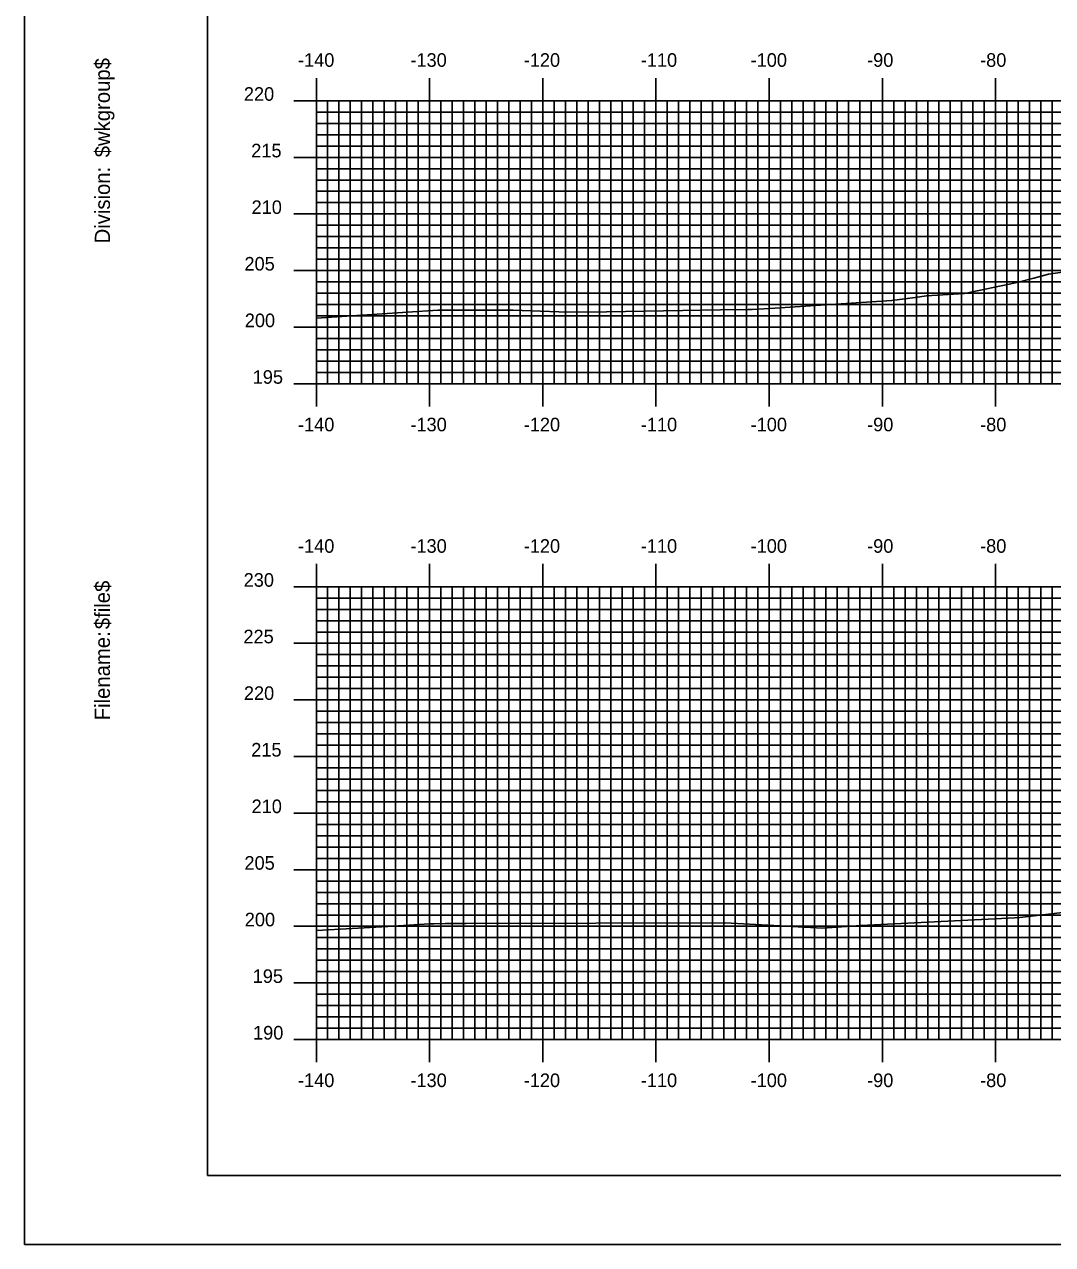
# Model space of a CAD drawing. Extents: x 852529 to 852872, y 364785 to 365005.
# Drawn here: x 852528.9 to 852619.8, y 364785.1 to 364892.9 of the extents above; entities that cross this region are included whole.
import ezdxf

# ---------------------------------------------------------------- set-up
doc = ezdxf.new("R2010")
doc.units = 0
for name, color, linetype in [('BORDER', 7, 'Continuous'), ('H_V ANNOTATION', 7, 'Continuous'), ('MAJOR', 7, 'Continuous'), ('MINOR', 7, 'Continuous'), ('PLOT BOUNDARY', 7, 'Continuous'), ('S_Roadway_Centerline', 7, 'Continuous')]:
    doc.layers.add(name, color=color, linetype=linetype)

msp = doc.modelspace()

# ---------------------------------------------------------------- linework, layer by layer
at = {"layer": 'BORDER'}
msp.add_lwpolyline([(852545.13, 364791.23), (852865.13, 364791.23), (852865.13, 365001.23), (852545.13, 365001.23)], close=True, dxfattribs=at)
at = {"layer": 'MAJOR'}
for p, q in [((852554.73, 364888.17), (852554.73, 364886.16)), ((852564.73, 364888.17), (852564.73, 364886.16)), ((852574.73, 364888.17), (852574.73, 364886.16)), ((852584.73, 364888.17), (852584.73, 364886.16)), ((852594.73, 364888.17), (852594.73, 364886.16)), ((852604.73, 364888.17), (852604.73, 364886.16)), ((852614.73, 364888.17), (852614.73, 364886.16)), ((852552.73, 364886.16), (852554.73, 364886.16)), ((852554.73, 364886.16), (852694.73, 364886.16)), ((852554.73, 364861.16), (852554.73, 364886.16)), ((852554.73, 364861.16), (852554.73, 364886.16)), ((852554.73, 364886.16), (852694.73, 364886.16)), ((852564.73, 364861.16), (852564.73, 364886.16)), ((852574.73, 364861.16), (852574.73, 364886.16)), ((852584.73, 364861.16), (852584.73, 364886.16)), ((852594.73, 364861.16), (852594.73, 364886.16)), ((852604.73, 364861.16), (852604.73, 364886.16)), ((852614.73, 364861.16), (852614.73, 364886.16)), ((852552.73, 364881.16), (852554.73, 364881.16)), ((852554.73, 364881.16), (852694.73, 364881.16)), ((852552.73, 364876.16), (852554.73, 364876.16)), ((852554.73, 364876.16), (852694.73, 364876.16)), ((852552.73, 364871.16), (852554.73, 364871.16)), ((852554.73, 364871.16), (852694.73, 364871.16)), ((852552.73, 364866.16), (852554.73, 364866.16)), ((852554.73, 364866.16), (852694.73, 364866.16)), ((852552.73, 364861.16), (852554.73, 364861.16)), ((852554.73, 364861.16), (852694.73, 364861.16)), ((852554.73, 364861.16), (852694.73, 364861.16)), ((852554.73, 364859.16), (852554.73, 364861.16)), ((852564.73, 364859.16), (852564.73, 364861.16)), ((852574.73, 364859.16), (852574.73, 364861.16)), ((852584.73, 364859.16), (852584.73, 364861.16)), ((852594.73, 364859.16), (852594.73, 364861.16)), ((852604.73, 364859.16), (852604.73, 364861.16)), ((852614.73, 364859.16), (852614.73, 364861.16)), ((852554.73, 364845.24), (852554.73, 364843.23)), ((852564.73, 364845.24), (852564.73, 364843.23)), ((852574.73, 364845.24), (852574.73, 364843.23)), ((852584.73, 364845.24), (852584.73, 364843.23)), ((852594.73, 364845.24), (852594.73, 364843.23)), ((852604.73, 364845.24), (852604.73, 364843.23)), ((852614.73, 364845.24), (852614.73, 364843.23)), ((852552.73, 364843.23), (852554.73, 364843.23)), ((852554.73, 364843.23), (852834.73, 364843.23)), ((852554.73, 364803.23), (852554.73, 364843.23)), ((852554.73, 364803.23), (852554.73, 364843.23)), ((852554.73, 364843.23), (852834.73, 364843.23)), ((852564.73, 364803.23), (852564.73, 364843.23)), ((852574.73, 364803.23), (852574.73, 364843.23)), ((852584.73, 364803.23), (852584.73, 364843.23)), ((852594.73, 364803.23), (852594.73, 364843.23)), ((852604.73, 364803.23), (852604.73, 364843.23)), ((852614.73, 364803.23), (852614.73, 364843.23)), ((852552.73, 364838.23), (852554.73, 364838.23)), ((852554.73, 364838.23), (852834.73, 364838.23)), ((852552.73, 364833.23), (852554.73, 364833.23)), ((852554.73, 364833.23), (852834.73, 364833.23)), ((852552.73, 364828.23), (852554.73, 364828.23)), ((852554.73, 364828.23), (852834.73, 364828.23)), ((852552.73, 364823.23), (852554.73, 364823.23)), ((852554.73, 364823.23), (852834.73, 364823.23)), ((852552.73, 364818.23), (852554.73, 364818.23)), ((852554.73, 364818.23), (852834.73, 364818.23)), ((852552.73, 364813.23), (852554.73, 364813.23)), ((852554.73, 364813.23), (852834.73, 364813.23)), ((852552.73, 364808.23), (852554.73, 364808.23)), ((852554.73, 364808.23), (852834.73, 364808.23)), ((852552.73, 364803.23), (852554.73, 364803.23)), ((852554.73, 364803.23), (852834.73, 364803.23)), ((852554.73, 364803.23), (852834.73, 364803.23)), ((852554.73, 364801.23), (852554.73, 364803.23)), ((852564.73, 364801.23), (852564.73, 364803.23)), ((852574.73, 364801.23), (852574.73, 364803.23)), ((852584.73, 364801.23), (852584.73, 364803.23)), ((852594.73, 364801.23), (852594.73, 364803.23)), ((852604.73, 364801.23), (852604.73, 364803.23)), ((852614.73, 364801.23), (852614.73, 364803.23))]:
    msp.add_line(p, q, dxfattribs=at)
at = {"layer": 'MINOR'}
for p, q in [((852555.73, 364861.16), (852555.73, 364886.16)), ((852556.73, 364861.16), (852556.73, 364886.16)), ((852557.73, 364861.16), (852557.73, 364886.16)), ((852558.73, 364861.16), (852558.73, 364886.16)), ((852559.73, 364861.16), (852559.73, 364886.16)), ((852560.73, 364861.16), (852560.73, 364886.16)), ((852561.73, 364861.16), (852561.73, 364886.16)), ((852562.73, 364861.16), (852562.73, 364886.16)), ((852563.73, 364861.16), (852563.73, 364886.16)), ((852565.73, 364861.16), (852565.73, 364886.16)), ((852566.73, 364861.16), (852566.73, 364886.16)), ((852567.73, 364861.16), (852567.73, 364886.16)), ((852568.73, 364861.16), (852568.73, 364886.16)), ((852569.73, 364861.16), (852569.73, 364886.16)), ((852570.73, 364861.16), (852570.73, 364886.16)), ((852571.73, 364861.16), (852571.73, 364886.16)), ((852572.73, 364861.16), (852572.73, 364886.16)), ((852573.73, 364861.16), (852573.73, 364886.16)), ((852575.73, 364861.16), (852575.73, 364886.16)), ((852576.73, 364861.16), (852576.73, 364886.16)), ((852577.73, 364861.16), (852577.73, 364886.16)), ((852578.73, 364861.16), (852578.73, 364886.16)), ((852579.73, 364861.16), (852579.73, 364886.16)), ((852580.73, 364861.16), (852580.73, 364886.16)), ((852581.73, 364861.16), (852581.73, 364886.16)), ((852582.73, 364861.16), (852582.73, 364886.16)), ((852583.73, 364861.16), (852583.73, 364886.16)), ((852585.73, 364861.16), (852585.73, 364886.16)), ((852586.73, 364861.16), (852586.73, 364886.16)), ((852587.73, 364861.16), (852587.73, 364886.16)), ((852588.73, 364861.16), (852588.73, 364886.16)), ((852589.73, 364861.16), (852589.73, 364886.16)), ((852590.73, 364861.16), (852590.73, 364886.16)), ((852591.73, 364861.16), (852591.73, 364886.16)), ((852592.73, 364861.16), (852592.73, 364886.16)), ((852593.73, 364861.16), (852593.73, 364886.16)), ((852595.73, 364861.16), (852595.73, 364886.16)), ((852596.73, 364861.16), (852596.73, 364886.16)), ((852597.73, 364861.16), (852597.73, 364886.16)), ((852598.73, 364861.16), (852598.73, 364886.16)), ((852599.73, 364861.16), (852599.73, 364886.16)), ((852600.73, 364861.16), (852600.73, 364886.16)), ((852601.73, 364861.16), (852601.73, 364886.16)), ((852602.73, 364861.16), (852602.73, 364886.16)), ((852603.73, 364861.16), (852603.73, 364886.16)), ((852605.73, 364861.16), (852605.73, 364886.16)), ((852606.73, 364861.16), (852606.73, 364886.16)), ((852607.73, 364861.16), (852607.73, 364886.16)), ((852608.73, 364861.16), (852608.73, 364886.16)), ((852609.73, 364861.16), (852609.73, 364886.16)), ((852610.73, 364861.16), (852610.73, 364886.16)), ((852611.73, 364861.16), (852611.73, 364886.16)), ((852612.73, 364861.16), (852612.73, 364886.16)), ((852613.73, 364861.16), (852613.73, 364886.16)), ((852615.73, 364861.16), (852615.73, 364886.16)), ((852616.73, 364861.16), (852616.73, 364886.16)), ((852617.73, 364861.16), (852617.73, 364886.16)), ((852618.73, 364861.16), (852618.73, 364886.16)), ((852619.73, 364861.16), (852619.73, 364886.16)), ((852554.73, 364885.16), (852694.73, 364885.16)), ((852554.73, 364885.16), (852556.73, 364885.16)), ((852554.73, 364884.16), (852694.73, 364884.16)), ((852554.73, 364884.16), (852556.73, 364884.16)), ((852554.73, 364883.16), (852694.73, 364883.16)), ((852554.73, 364883.16), (852556.73, 364883.16)), ((852554.73, 364882.16), (852694.73, 364882.16)), ((852554.73, 364882.16), (852556.73, 364882.16)), ((852554.73, 364880.16), (852694.73, 364880.16)), ((852554.73, 364880.16), (852556.73, 364880.16)), ((852554.73, 364879.16), (852694.73, 364879.16)), ((852554.73, 364879.16), (852556.73, 364879.16)), ((852554.73, 364878.16), (852694.73, 364878.16)), ((852554.73, 364878.16), (852556.73, 364878.16)), ((852554.73, 364877.16), (852694.73, 364877.16)), ((852554.73, 364877.16), (852556.73, 364877.16)), ((852554.73, 364875.16), (852694.73, 364875.16)), ((852554.73, 364875.16), (852556.73, 364875.16)), ((852554.73, 364874.16), (852694.73, 364874.16)), ((852554.73, 364874.16), (852556.73, 364874.16)), ((852554.73, 364873.16), (852694.73, 364873.16)), ((852554.73, 364873.16), (852556.73, 364873.16)), ((852554.73, 364872.16), (852694.73, 364872.16)), ((852554.73, 364872.16), (852556.73, 364872.16)), ((852554.73, 364870.16), (852694.73, 364870.16)), ((852554.73, 364870.16), (852556.73, 364870.16)), ((852554.73, 364869.16), (852694.73, 364869.16)), ((852554.73, 364869.16), (852556.73, 364869.16)), ((852554.73, 364868.16), (852694.73, 364868.16)), ((852554.73, 364868.16), (852556.73, 364868.16)), ((852554.73, 364867.16), (852694.73, 364867.16)), ((852554.73, 364867.16), (852556.73, 364867.16)), ((852554.73, 364865.16), (852694.73, 364865.16)), ((852554.73, 364865.16), (852556.73, 364865.16)), ((852554.73, 364864.16), (852694.73, 364864.16)), ((852554.73, 364864.16), (852556.73, 364864.16)), ((852554.73, 364863.16), (852694.73, 364863.16)), ((852554.73, 364863.16), (852556.73, 364863.16)), ((852554.73, 364862.16), (852694.73, 364862.16)), ((852554.73, 364862.16), (852556.73, 364862.16)), ((852555.73, 364803.23), (852555.73, 364843.23)), ((852556.73, 364803.23), (852556.73, 364843.23)), ((852557.73, 364803.23), (852557.73, 364843.23)), ((852558.73, 364803.23), (852558.73, 364843.23)), ((852559.73, 364803.23), (852559.73, 364843.23)), ((852560.73, 364803.23), (852560.73, 364843.23)), ((852561.73, 364803.23), (852561.73, 364843.23)), ((852562.73, 364803.23), (852562.73, 364843.23)), ((852563.73, 364803.23), (852563.73, 364843.23)), ((852565.73, 364803.23), (852565.73, 364843.23)), ((852566.73, 364803.23), (852566.73, 364843.23)), ((852567.73, 364803.23), (852567.73, 364843.23)), ((852568.73, 364803.23), (852568.73, 364843.23)), ((852569.73, 364803.23), (852569.73, 364843.23)), ((852570.73, 364803.23), (852570.73, 364843.23)), ((852571.73, 364803.23), (852571.73, 364843.23)), ((852572.73, 364803.23), (852572.73, 364843.23)), ((852573.73, 364803.23), (852573.73, 364843.23)), ((852575.73, 364803.23), (852575.73, 364843.23)), ((852576.73, 364803.23), (852576.73, 364843.23)), ((852577.73, 364803.23), (852577.73, 364843.23)), ((852578.73, 364803.23), (852578.73, 364843.23)), ((852579.73, 364803.23), (852579.73, 364843.23)), ((852580.73, 364803.23), (852580.73, 364843.23)), ((852581.73, 364803.23), (852581.73, 364843.23)), ((852582.73, 364803.23), (852582.73, 364843.23)), ((852583.73, 364803.23), (852583.73, 364843.23)), ((852585.73, 364803.23), (852585.73, 364843.23)), ((852586.73, 364803.23), (852586.73, 364843.23)), ((852587.73, 364803.23), (852587.73, 364843.23)), ((852588.73, 364803.23), (852588.73, 364843.23)), ((852589.73, 364803.23), (852589.73, 364843.23)), ((852590.73, 364803.23), (852590.73, 364843.23)), ((852591.73, 364803.23), (852591.73, 364843.23)), ((852592.73, 364803.23), (852592.73, 364843.23)), ((852593.73, 364803.23), (852593.73, 364843.23)), ((852595.73, 364803.23), (852595.73, 364843.23)), ((852596.73, 364803.23), (852596.73, 364843.23)), ((852597.73, 364803.23), (852597.73, 364843.23)), ((852598.73, 364803.23), (852598.73, 364843.23)), ((852599.73, 364803.23), (852599.73, 364843.23)), ((852600.73, 364803.23), (852600.73, 364843.23)), ((852601.73, 364803.23), (852601.73, 364843.23)), ((852602.73, 364803.23), (852602.73, 364843.23)), ((852603.73, 364803.23), (852603.73, 364843.23)), ((852605.73, 364803.23), (852605.73, 364843.23)), ((852606.73, 364803.23), (852606.73, 364843.23)), ((852607.73, 364803.23), (852607.73, 364843.23)), ((852608.73, 364803.23), (852608.73, 364843.23)), ((852609.73, 364803.23), (852609.73, 364843.23)), ((852610.73, 364803.23), (852610.73, 364843.23)), ((852611.73, 364803.23), (852611.73, 364843.23)), ((852612.73, 364803.23), (852612.73, 364843.23)), ((852613.73, 364803.23), (852613.73, 364843.23)), ((852615.73, 364803.23), (852615.73, 364843.23)), ((852616.73, 364803.23), (852616.73, 364843.23)), ((852617.73, 364803.23), (852617.73, 364843.23)), ((852618.73, 364803.23), (852618.73, 364843.23)), ((852619.73, 364803.23), (852619.73, 364843.23)), ((852554.73, 364842.23), (852834.73, 364842.23)), ((852554.73, 364842.23), (852556.73, 364842.23)), ((852554.73, 364841.23), (852834.73, 364841.23)), ((852554.73, 364841.23), (852556.73, 364841.23)), ((852554.73, 364840.23), (852834.73, 364840.23)), ((852554.73, 364840.23), (852556.73, 364840.23)), ((852554.73, 364839.23), (852834.73, 364839.23)), ((852554.73, 364839.23), (852556.73, 364839.23)), ((852554.73, 364837.23), (852834.73, 364837.23)), ((852554.73, 364837.23), (852556.73, 364837.23)), ((852554.73, 364836.23), (852834.73, 364836.23)), ((852554.73, 364836.23), (852556.73, 364836.23)), ((852554.73, 364835.23), (852834.73, 364835.23)), ((852554.73, 364835.23), (852556.73, 364835.23)), ((852554.73, 364834.23), (852834.73, 364834.23)), ((852554.73, 364834.23), (852556.73, 364834.23)), ((852554.73, 364832.23), (852834.73, 364832.23)), ((852554.73, 364832.23), (852556.73, 364832.23)), ((852554.73, 364831.23), (852834.73, 364831.23)), ((852554.73, 364831.23), (852556.73, 364831.23)), ((852554.73, 364830.23), (852834.73, 364830.23)), ((852554.73, 364830.23), (852556.73, 364830.23)), ((852554.73, 364829.23), (852834.73, 364829.23)), ((852554.73, 364829.23), (852556.73, 364829.23)), ((852554.73, 364827.23), (852834.73, 364827.23)), ((852554.73, 364827.23), (852556.73, 364827.23)), ((852554.73, 364826.23), (852834.73, 364826.23)), ((852554.73, 364826.23), (852556.73, 364826.23)), ((852554.73, 364825.23), (852834.73, 364825.23)), ((852554.73, 364825.23), (852556.73, 364825.23)), ((852554.73, 364824.23), (852834.73, 364824.23)), ((852554.73, 364824.23), (852556.73, 364824.23)), ((852554.73, 364822.23), (852834.73, 364822.23)), ((852554.73, 364822.23), (852556.73, 364822.23)), ((852554.73, 364821.23), (852834.73, 364821.23)), ((852554.73, 364821.23), (852556.73, 364821.23)), ((852554.73, 364820.23), (852834.73, 364820.23)), ((852554.73, 364820.23), (852556.73, 364820.23)), ((852554.73, 364819.23), (852834.73, 364819.23)), ((852554.73, 364819.23), (852556.73, 364819.23)), ((852554.73, 364817.23), (852834.73, 364817.23)), ((852554.73, 364817.23), (852556.73, 364817.23)), ((852554.73, 364816.23), (852834.73, 364816.23)), ((852554.73, 364816.23), (852556.73, 364816.23)), ((852554.73, 364815.23), (852834.73, 364815.23)), ((852554.73, 364815.23), (852556.73, 364815.23)), ((852554.73, 364814.23), (852834.73, 364814.23)), ((852554.73, 364814.23), (852556.73, 364814.23)), ((852554.73, 364812.23), (852834.73, 364812.23)), ((852554.73, 364812.23), (852556.73, 364812.23)), ((852554.73, 364811.23), (852834.73, 364811.23)), ((852554.73, 364811.23), (852556.73, 364811.23)), ((852554.73, 364810.23), (852834.73, 364810.23)), ((852554.73, 364810.23), (852556.73, 364810.23)), ((852554.73, 364809.23), (852834.73, 364809.23)), ((852554.73, 364809.23), (852556.73, 364809.23)), ((852554.73, 364807.23), (852834.73, 364807.23)), ((852554.73, 364807.23), (852556.73, 364807.23)), ((852554.73, 364806.23), (852834.73, 364806.23)), ((852554.73, 364806.23), (852556.73, 364806.23)), ((852554.73, 364805.23), (852834.73, 364805.23)), ((852554.73, 364805.23), (852556.73, 364805.23)), ((852554.73, 364804.23), (852834.73, 364804.23)), ((852554.73, 364804.23), (852556.73, 364804.23))]:
    msp.add_line(p, q, dxfattribs=at)
at = {"layer": 'PLOT BOUNDARY'}
msp.add_lwpolyline([(852528.94, 364785.11), (852868.94, 364785.11), (852868.94, 365005.11), (852528.94, 365005.11)], close=True, dxfattribs=at)
at = {"layer": 'S_Roadway_Centerline'}
for points in [[(852554.73, 364866.96), (852565.45, 364867.67), (852572.13, 364867.66), (852576.15, 364867.52), (852578.68, 364867.5), (852590.44, 364867.69), (852592.87, 364867.72), (852593.23, 364867.72), (852594.79, 364867.82), (852605.57, 364868.52), (852607.62, 364868.79), (852608.64, 364868.94), (852611.97, 364869.12), (852616.49, 364870.08), (852618.11, 364870.5), (852619.4, 364870.83), (852624.83, 364871.6)], [(852554.73, 364812.87), (852561.04, 364813.22), (852564.73, 364813.46), (852565.12, 364813.46), (852566.11, 364813.47), (852567.97, 364813.48), (852590.83, 364813.53), (852599.44, 364813.07), (852602.84, 364813.31), (852616.43, 364813.97), (852616.86, 364814), (852625.43, 364815.02)]]:
    msp.add_lwpolyline(points, dxfattribs=at)

# ---------------------------------------------------------------- texts
at = {"layer": 'BORDER'}
for s, p in [('$wkgroup$', (852536.5, 364881.17)), ('Division:', (852536.5, 364873.56)), ('$file$', (852536.5, 364839.48)), ('Filename:', (852536.5, 364831.43))]:
    msp.add_text(s, height=1.339, rotation=90, dxfattribs=at).set_placement(p)
at = {"layer": 'H_V ANNOTATION'}
for s, p in [('-140', (852553.11, 364889.16)), ('-130', (852563.04, 364889.16)), ('-120', (852573.05, 364889.16)), ('-110', (852583.39, 364889.16)), ('-100', (852593.09, 364889.16)), ('-90', (852603.38, 364889.16)), ('-80', (852613.36, 364889.16)), ('220', (852548.33, 364886.16)), ('215', (852548.98, 364881.16)), ('210', (852549.01, 364876.16)), ('205', (852548.38, 364871.16)), ('200', (852548.41, 364866.16)), ('195', (852549.11, 364861.16)), ('-140', (852553.11, 364856.96)), ('-130', (852563.04, 364856.96)), ('-120', (852573.05, 364856.96)), ('-110', (852583.39, 364856.96)), ('-100', (852593.09, 364856.96)), ('-90', (852603.38, 364856.96)), ('-80', (852613.36, 364856.96)), ('-140', (852553.11, 364846.23)), ('-130', (852563.04, 364846.23)), ('-120', (852573.05, 364846.23)), ('-110', (852583.39, 364846.23)), ('-100', (852593.09, 364846.23)), ('-90', (852603.38, 364846.23)), ('-80', (852613.36, 364846.23)), ('230', (852548.31, 364843.23)), ('225', (852548.29, 364838.23)), ('220', (852548.33, 364833.23)), ('215', (852548.98, 364828.23)), ('210', (852549.01, 364823.23)), ('205', (852548.38, 364818.23)), ('200', (852548.41, 364813.23)), ('195', (852549.11, 364808.23)), ('190', (852549.14, 364803.23)), ('-140', (852553.11, 364799.03)), ('-130', (852563.04, 364799.03)), ('-120', (852573.05, 364799.03)), ('-110', (852583.39, 364799.03)), ('-100', (852593.09, 364799.03)), ('-90', (852603.38, 364799.03)), ('-80', (852613.36, 364799.03))]:
    msp.add_text(s, height=1.2, dxfattribs=at).set_placement(p)
at = {"layer": 'MAJOR'}
for p in [(852554.72, 364861.16), (852554.72, 364803.23)]:
    msp.add_text('-', height=0.012, dxfattribs=at).set_placement(p)

doc.saveas('drawing.dxf')
